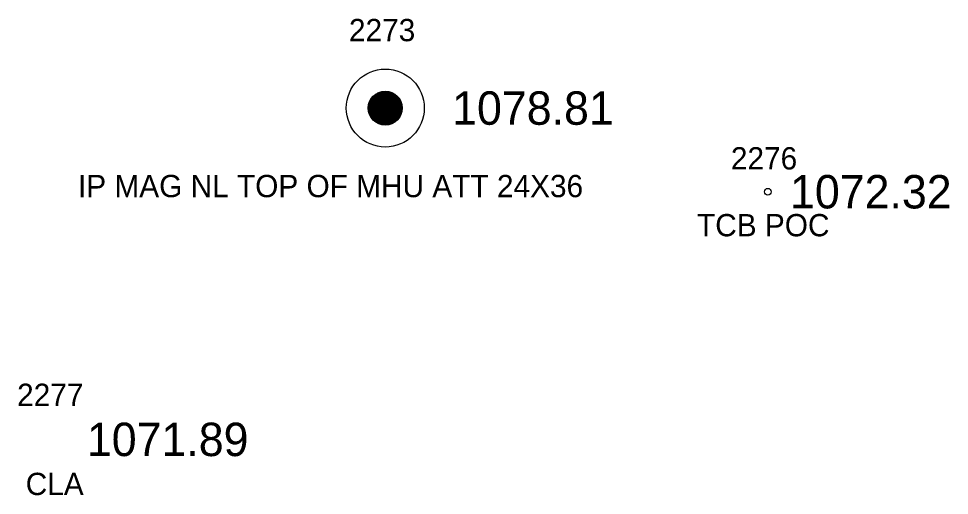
# Model space of a CAD drawing. Extents: x 1578957 to 1581675, y 1115963 to 1120391.
# Drawn here: x 1580092.86 to 1580134.62, y 1116308.35 to 1116329.74 of the extents above; entities that cross this region are included whole.
import ezdxf

# ---------------------------------------------------------------- set-up
doc = ezdxf.new("R2010")
doc.units = 0
for name, color, linetype in [('RD_EX_Conc_txCode', 7, 'Continuous'), ('RD_EX_DV_Prop_txCode', 7, 'Continuous'), ('RD_EX_DV_PropPin', 7, 'Continuous'), ('RD_EX_TX_Conc_ELEV', 7, 'Continuous'), ('RD_EX_TX_DV_Prop_ELEV', 7, 'Continuous'), ('RD_HC_Survey_ELEV', 7, 'Continuous'), ('RD_HC_Survey_txCode', 7, 'Continuous'), ('RD_SMD_Locator', 7, 'Continuous')]:
    doc.layers.add(name, color=color, linetype=linetype)

msp = doc.modelspace()

# ---------------------------------------------------------------- linework, layer by layer
at = {"layer": 'RD_EX_DV_PropPin'}
for p, q in [((1580108.857, 1116325.12), (1580108.857, 1116326.339)), ((1580108.892, 1116325.095), (1580108.892, 1116326.364)), ((1580108.927, 1116325.073), (1580108.927, 1116326.386)), ((1580108.962, 1116325.054), (1580108.962, 1116326.405)), ((1580108.997, 1116325.037), (1580108.997, 1116326.422)), ((1580109.032, 1116325.022), (1580109.032, 1116326.437)), ((1580109.067, 1116325.009), (1580109.067, 1116326.45)), ((1580109.102, 1116324.998), (1580109.102, 1116326.461)), ((1580109.137, 1116324.989), (1580109.137, 1116326.47)), ((1580109.172, 1116324.982), (1580109.172, 1116326.478)), ((1580109.207, 1116324.976), (1580109.207, 1116326.483)), ((1580109.242, 1116324.972), (1580109.242, 1116326.487)), ((1580109.277, 1116324.969), (1580109.277, 1116326.49)), ((1580109.312, 1116324.969), (1580109.312, 1116326.491)), ((1580109.347, 1116324.969), (1580109.347, 1116326.49)), ((1580109.382, 1116324.972), (1580109.382, 1116326.487)), ((1580109.417, 1116324.976), (1580109.417, 1116326.483)), ((1580109.452, 1116324.982), (1580109.452, 1116326.478)), ((1580109.487, 1116324.989), (1580109.487, 1116326.47)), ((1580109.522, 1116324.998), (1580109.522, 1116326.461)), ((1580109.557, 1116325.009), (1580109.557, 1116326.45)), ((1580109.592, 1116325.022), (1580109.592, 1116326.437)), ((1580109.628, 1116325.037), (1580109.628, 1116326.422)), ((1580109.663, 1116325.054), (1580109.663, 1116326.405)), ((1580109.698, 1116325.073), (1580109.698, 1116326.386)), ((1580109.733, 1116325.095), (1580109.733, 1116326.364)), ((1580109.768, 1116325.12), (1580109.768, 1116326.339)), ((1580108.577, 1116325.533), (1580108.577, 1116325.926)), ((1580108.612, 1116325.432), (1580108.612, 1116326.028)), ((1580108.647, 1116325.36), (1580108.647, 1116326.099)), ((1580108.682, 1116325.303), (1580108.682, 1116326.156)), ((1580108.717, 1116325.255), (1580108.717, 1116326.204)), ((1580108.752, 1116325.215), (1580108.752, 1116326.245)), ((1580108.787, 1116325.179), (1580108.787, 1116326.28)), ((1580108.822, 1116325.147), (1580108.822, 1116326.312)), ((1580109.803, 1116325.147), (1580109.803, 1116326.312)), ((1580109.838, 1116325.179), (1580109.838, 1116326.28)), ((1580109.873, 1116325.215), (1580109.873, 1116326.245)), ((1580109.908, 1116325.255), (1580109.908, 1116326.204)), ((1580109.943, 1116325.303), (1580109.943, 1116326.156)), ((1580109.978, 1116325.36), (1580109.978, 1116326.099)), ((1580110.013, 1116325.432), (1580110.013, 1116326.028)), ((1580110.048, 1116325.533), (1580110.048, 1116325.926))]:
    msp.add_line(p, q, dxfattribs=at)
for radius in [1.75, 0.761]:
    msp.add_circle((1580109.312, 1116325.73), radius, dxfattribs=at)
at = {"layer": 'RD_SMD_Locator'}
for centre in [(1580109.312, 1116325.73), (1580126.472, 1116321.975)]:
    msp.add_circle(centre, 0.15, dxfattribs=at)

# ---------------------------------------------------------------- texts
at = {"layer": 'RD_EX_Conc_txCode'}
for s, p in [('2276', (1580124.818, 1116322.975)), ('TCB POC', (1580123.298, 1116319.975))]:
    msp.add_text(s, height=1, dxfattribs=at).set_placement(p)
at = {"layer": 'RD_EX_DV_Prop_txCode'}
for s, p in [('2273', (1580107.682, 1116328.73)), ('IP MAG NL TOP OF MHU ATT 24X36', (1580095.525, 1116321.73))]:
    msp.add_text(s, height=1, dxfattribs=at).set_placement(p)
at = {"layer": 'RD_EX_TX_Conc_ELEV'}
msp.add_text('1072.32', height=1.5, dxfattribs=at).set_placement((1580127.472, 1116321.225))
at = {"layer": 'RD_EX_TX_DV_Prop_ELEV'}
msp.add_text('1078.81', height=1.5, dxfattribs=at).set_placement((1580112.312, 1116324.98))
at = {"layer": 'RD_HC_Survey_ELEV'}
msp.add_text('1071.89', height=1.5, dxfattribs=at).set_placement((1580095.924, 1116310.111))
at = {"layer": 'RD_HC_Survey_txCode'}
for s, p in [('2277', (1580092.794, 1116312.361)), ('CLA', (1580093.18, 1116308.361))]:
    msp.add_text(s, height=1, dxfattribs=at).set_placement(p)

doc.saveas('drawing.dxf')
